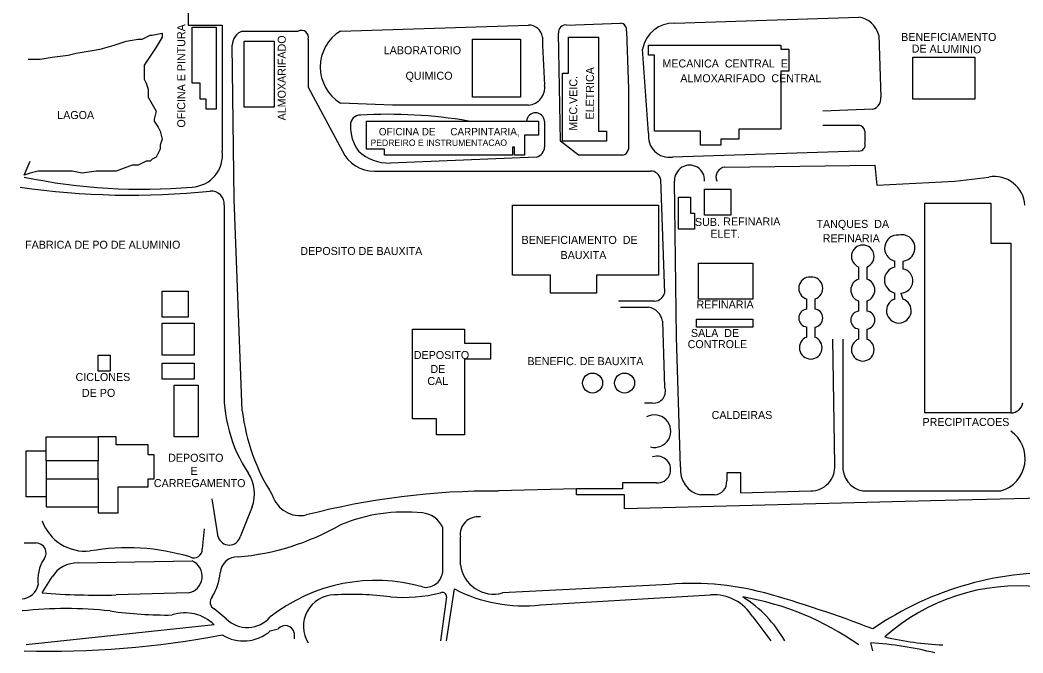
# Model space of a CAD drawing. Extents: x 325899 to 363134, y 7578590 to 7592502.
# Drawn here: x 335293 to 335794, y 7583508 to 7583824 of the extents above; entities that cross this region are included whole.
import ezdxf

# ---------------------------------------------------------------- set-up
doc = ezdxf.new("R2010")
doc.units = 0
for name, color, linetype in [('EDIFEXISTENT', 7, 'Continuous'), ('EDIFIDENTIF', 7, 'Continuous'), ('EDIFOBRAEXIS', 7, 'Continuous')]:
    doc.layers.add(name, color=color, linetype=linetype)

msp = doc.modelspace()

# ---------------------------------------------------------------- linework, layer by layer
at = {"layer": 'EDIFEXISTENT'}
for p, q in [((335379.39, 7583820.91), (335391.39, 7583820.91)), ((335379.39, 7583792.91), (335379.39, 7583820.91)), ((335391.39, 7583820.91), (335391.39, 7583779.91)), ((335405.39, 7583813.91), (335420.39, 7583813.91)), ((335405.39, 7583780.91), (335405.39, 7583813.91)), ((335420.39, 7583813.91), (335420.39, 7583780.91)), ((335519.39, 7583814.91), (335543.39, 7583814.91)), ((335519.39, 7583785.91), (335519.39, 7583814.91)), ((335543.39, 7583814.91), (335543.39, 7583785.91)), ((335567.39, 7583815.91), (335582.39, 7583815.91)), ((335567.39, 7583797.91), (335567.39, 7583815.91)), ((335582.39, 7583815.91), (335582.39, 7583768.91)), ((335607.39, 7583811.91), (335673.39, 7583811.91)), ((335607.39, 7583806.91), (335607.39, 7583811.91)), ((335673.39, 7583811.91), (335673.39, 7583809.91)), ((335673.39, 7583809.91), (335677.39, 7583809.91)), ((335677.39, 7583809.91), (335677.39, 7583798.91)), ((335610.39, 7583806.91), (335607.39, 7583806.91)), ((335610.39, 7583768.91), (335610.39, 7583806.91)), ((335739.39, 7583805.91), (335770.39, 7583805.91)), ((335739.39, 7583784.91), (335739.39, 7583805.91)), ((335770.39, 7583805.91), (335770.39, 7583784.91)), ((335564.39, 7583763.91), (335564.39, 7583797.91)), ((335564.39, 7583797.91), (335567.39, 7583797.91)), ((335677.39, 7583798.91), (335673.39, 7583798.91)), ((335673.39, 7583798.91), (335673.39, 7583769.91)), ((335383.39, 7583792.91), (335379.39, 7583792.91)), ((335383.39, 7583784.91), (335383.39, 7583792.91)), ((335386.39, 7583784.91), (335383.39, 7583784.91)), ((335386.39, 7583779.91), (335386.39, 7583784.91)), ((335543.39, 7583785.91), (335519.39, 7583785.91)), ((335770.39, 7583784.91), (335739.39, 7583784.91)), ((335391.39, 7583779.91), (335386.39, 7583779.91)), ((335420.39, 7583780.91), (335405.39, 7583780.91)), ((335466.39, 7583759.91), (335466.39, 7583773.91)), ((335466.39, 7583773.91), (335550.39, 7583773.91)), ((335550.39, 7583773.91), (335552.39, 7583773.91)), ((335552.39, 7583773.91), (335552.39, 7583766.91)), ((335582.39, 7583768.91), (335586.39, 7583768.91)), ((335586.39, 7583768.91), (335586.39, 7583763.91)), ((335633.39, 7583768.91), (335610.39, 7583768.91)), ((335633.39, 7583761.91), (335633.39, 7583768.91)), ((335673.39, 7583769.91), (335652.39, 7583769.91)), ((335652.39, 7583769.91), (335652.39, 7583764.91)), ((335552.39, 7583766.91), (335545.39, 7583766.91)), ((335545.39, 7583766.91), (335545.39, 7583756.91)), ((335586.39, 7583763.91), (335564.39, 7583763.91)), ((335652.39, 7583764.91), (335643.39, 7583764.91)), ((335643.39, 7583764.91), (335643.39, 7583761.91)), ((335475.39, 7583759.91), (335466.39, 7583759.91)), ((335475.39, 7583756.91), (335475.39, 7583759.91)), ((335540.39, 7583760.91), (335539.39, 7583760.91)), ((335539.39, 7583760.91), (335539.39, 7583756.91)), ((335540.39, 7583756.91), (335540.39, 7583760.91)), ((335643.39, 7583761.91), (335633.39, 7583761.91)), ((335539.39, 7583756.91), (335475.39, 7583756.91)), ((335545.39, 7583756.91), (335540.39, 7583756.91)), ((335635.39, 7583726.91), (335635.39, 7583739.91)), ((335635.39, 7583739.91), (335648.39, 7583739.91)), ((335648.39, 7583739.91), (335648.39, 7583726.91)), ((335622.39, 7583735.91), (335628.39, 7583735.91)), ((335622.39, 7583719.91), (335622.39, 7583735.91)), ((335628.39, 7583735.91), (335628.39, 7583727.91)), ((335745.39, 7583732.91), (335778.39, 7583732.91)), ((335745.39, 7583627.91), (335745.39, 7583732.91)), ((335778.39, 7583732.91), (335778.39, 7583712.91)), ((335539.39, 7583731.91), (335612.39, 7583731.91)), ((335539.39, 7583696.91), (335539.39, 7583731.91)), ((335612.39, 7583731.91), (335612.39, 7583696.91)), ((335628.39, 7583727.91), (335630.39, 7583727.91)), ((335630.39, 7583727.91), (335630.39, 7583719.91)), ((335648.39, 7583726.91), (335635.39, 7583726.91)), ((335630.39, 7583719.91), (335622.39, 7583719.91)), ((335778.39, 7583712.91), (335788.39, 7583712.91)), ((335788.39, 7583712.91), (335788.39, 7583627.91)), ((335632.39, 7583702.91), (335659.39, 7583702.91)), ((335632.39, 7583684.91), (335632.39, 7583702.91)), ((335659.39, 7583702.91), (335659.39, 7583684.91)), ((335730.39, 7583700.91), (335730.39, 7583703.91)), ((335734.39, 7583703.91), (335734.39, 7583699.91)), ((335712.39, 7583694.91), (335712.39, 7583700.91)), ((335716.39, 7583700.91), (335716.39, 7583694.91)), ((335558.39, 7583696.91), (335539.39, 7583696.91)), ((335558.39, 7583687.91), (335558.39, 7583696.91)), ((335612.39, 7583696.91), (335581.39, 7583696.91)), ((335581.39, 7583696.91), (335581.39, 7583687.91)), ((335364.39, 7583688.91), (335377.39, 7583688.91)), ((335364.39, 7583675.91), (335364.39, 7583688.91)), ((335377.39, 7583688.91), (335377.39, 7583675.91)), ((335581.39, 7583687.91), (335558.39, 7583687.91)), ((335730.39, 7583684.91), (335730.39, 7583687.91)), ((335733.39, 7583687.91), (335734.39, 7583684.91)), ((335659.39, 7583684.91), (335632.39, 7583684.91)), ((335686.39, 7583679.91), (335686.39, 7583684.91)), ((335690.39, 7583684.91), (335690.39, 7583679.91)), ((335712.39, 7583678.91), (335712.39, 7583683.91)), ((335716.39, 7583683.91), (335716.39, 7583678.91)), ((335377.39, 7583675.91), (335364.39, 7583675.91)), ((335364.39, 7583672.91), (335380.39, 7583672.91)), ((335364.39, 7583656.91), (335364.39, 7583672.91)), ((335380.39, 7583672.91), (335380.39, 7583656.91)), ((335631.39, 7583674.91), (335659.39, 7583674.91)), ((335631.39, 7583670.91), (335631.39, 7583674.91)), ((335659.39, 7583674.91), (335659.39, 7583670.91)), ((335489.39, 7583669.91), (335515.39, 7583669.91)), ((335489.39, 7583624.91), (335489.39, 7583669.91)), ((335515.39, 7583669.91), (335515.39, 7583662.91)), ((335659.39, 7583670.91), (335631.39, 7583670.91)), ((335686.39, 7583665.91), (335686.39, 7583670.91)), ((335690.39, 7583670.91), (335690.39, 7583665.91)), ((335712.39, 7583664.91), (335712.39, 7583669.91)), ((335716.39, 7583669.91), (335716.39, 7583664.91)), ((335515.39, 7583662.91), (335528.39, 7583662.91)), ((335528.39, 7583662.91), (335528.39, 7583654.91)), ((335332.39, 7583656.91), (335338.39, 7583656.91)), ((335332.39, 7583648.91), (335332.39, 7583656.91)), ((335338.39, 7583656.91), (335338.39, 7583648.91)), ((335380.39, 7583656.91), (335364.39, 7583656.91)), ((335364.39, 7583656.91), (335364.39, 7583656.91)), ((335364.39, 7583652.91), (335380.39, 7583652.91)), ((335364.39, 7583644.91), (335364.39, 7583652.91)), ((335380.39, 7583652.91), (335380.39, 7583644.91)), ((335528.39, 7583654.91), (335515.39, 7583654.91)), ((335515.39, 7583654.91), (335515.39, 7583623.91)), ((335338.39, 7583648.91), (335332.39, 7583648.91)), ((335380.39, 7583644.91), (335364.39, 7583644.91)), ((335370.39, 7583641.91), (335382.39, 7583641.91)), ((335370.39, 7583615.91), (335370.39, 7583641.91)), ((335382.39, 7583641.91), (335382.39, 7583615.91)), ((335788.39, 7583627.91), (335745.39, 7583627.91)), ((335501.39, 7583624.91), (335489.39, 7583624.91)), ((335501.39, 7583616.91), (335501.39, 7583624.91)), ((335515.39, 7583623.91), (335515.39, 7583622.91)), ((335515.39, 7583622.91), (335515.39, 7583616.91)), ((335306.39, 7583608.91), (335306.39, 7583615.91)), ((335306.39, 7583615.91), (335332.39, 7583615.91)), ((335332.39, 7583615.91), (335332.39, 7583603.91)), ((335341.39, 7583615.91), (335332.39, 7583615.91)), ((335341.39, 7583611.91), (335341.39, 7583615.91)), ((335382.39, 7583615.91), (335370.39, 7583615.91)), ((335515.39, 7583616.91), (335501.39, 7583616.91)), ((335296.39, 7583585.91), (335296.39, 7583608.91)), ((335296.39, 7583608.91), (335306.39, 7583608.91)), ((335306.39, 7583603.91), (335306.39, 7583608.91)), ((335357.39, 7583611.91), (335341.39, 7583611.91)), ((335357.39, 7583606.91), (335357.39, 7583611.91)), ((335332.39, 7583603.91), (335306.39, 7583603.91)), ((335306.39, 7583603.91), (335306.39, 7583594.91)), ((335332.39, 7583594.91), (335332.39, 7583603.91)), ((335360.39, 7583606.91), (335357.39, 7583606.91)), ((335360.39, 7583594.91), (335360.39, 7583606.91)), ((335306.39, 7583594.91), (335332.39, 7583594.91)), ((335306.39, 7583594.91), (335306.39, 7583585.91)), ((335332.39, 7583594.91), (335332.39, 7583580.91)), ((335357.39, 7583590.91), (335357.39, 7583594.91)), ((335357.39, 7583594.91), (335360.39, 7583594.91)), ((335342.39, 7583577.91), (335342.39, 7583590.91)), ((335342.39, 7583590.91), (335357.39, 7583590.91)), ((335306.39, 7583585.91), (335296.39, 7583585.91)), ((335306.39, 7583585.91), (335306.39, 7583580.91)), ((335306.39, 7583580.91), (335332.39, 7583580.91)), ((335332.39, 7583580.91), (335332.39, 7583577.91)), ((335332.39, 7583577.91), (335342.39, 7583577.91))]:
    msp.add_line(p, q, dxfattribs=at)
for centre in [(335579.39, 7583642.91), (335595.39, 7583642.91)]:
    msp.add_circle(centre, 5, dxfattribs=at)
for centre, radius, start, end in [((335731.9, 7583710.33), 6.6, 85.7202, 256.7875), ((335733.85, 7583710.48), 6.59, 274.7414, 102.7509), ((335714.39, 7583706.23), 5.68, 290.6097, 249.3903), ((335731.86, 7583694.41), 6.66, 102.7386, 257.2614), ((335733.35, 7583693.96), 6.05, 270.4308, 80.0419), ((335688.02, 7583690.3), 5.63, 86.1782, 253.2121), ((335688.79, 7583690.3), 5.62, 286.5373, 94.0723), ((335714.17, 7583689.41), 5.78, 107.9453, 252.0547), ((335714.64, 7583689.41), 5.77, 287.6501, 72.3499), ((335732.39, 7583679.08), 6.17, 108.9246, 71.0754), ((335686.92, 7583675.41), 4.53, 96.7329, 263.2671), ((335689.89, 7583675.41), 4.53, 276.3402, 83.6598), ((335712.92, 7583674.41), 4.53, 96.7329, 263.2671), ((335715.89, 7583674.41), 4.53, 276.3402, 83.6598), ((335688.39, 7583660.59), 5.68, 110.6097, 69.3903), ((335714.39, 7583659.59), 5.68, 110.6097, 69.3903)]:
    msp.add_arc(centre, radius, start, end, dxfattribs=at)
at = {"layer": 'EDIFOBRAEXIS'}
for points in [[(335400.39, 7584001.91), (335410.39, 7583884.91), (335420.39, 7583864.91), (335395.39, 7583838.91), (335395.39, 7583828.91), (335377.39, 7583828.91), (335377.39, 7583821.91), (335394.39, 7583821.91), (335394.39, 7583758.91)], [(335566.39, 7583821.91), (335593.39, 7583822.91)], [(335620.39, 7583822.91), (335712.39, 7583825.91)], [(335297.39, 7583804.91), (335303.39, 7583804.91), (335309.39, 7583805.91), (335317.39, 7583806.91), (335321.39, 7583807.91), (335327.39, 7583808.91), (335333.39, 7583809.91), (335340.39, 7583811.91), (335346.39, 7583813.91), (335352.39, 7583814.91), (335354.39, 7583814.91), (335358.39, 7583816.91), (335359.39, 7583816.91), (335364.39, 7583817.91), (335364.39, 7583815.91), (335361.39, 7583810.91), (335359.39, 7583807.91), (335357.39, 7583804.91), (335355.39, 7583801.91), (335355.39, 7583799.91), (335355.39, 7583796.91), (335355.39, 7583794.91), (335356.39, 7583792.91), (335357.39, 7583789.91), (335357.39, 7583785.91), (335361.39, 7583778.91), (335360.39, 7583774.91), (335360.39, 7583773.91), (335362.39, 7583770.91), (335363.39, 7583768.91), (335364.39, 7583764.91), (335363.39, 7583761.91), (335363.39, 7583759.91), (335362.39, 7583757.91), (335361.39, 7583755.91), (335359.39, 7583754.91), (335358.39, 7583753.91), (335356.39, 7583753.91), (335352.39, 7583751.91), (335349.39, 7583751.91), (335341.39, 7583748.91), (335331.39, 7583748.91), (335324.39, 7583747.91), (335319.39, 7583748.91), (335312.39, 7583748.91), (335305.39, 7583748.91), (335302.39, 7583748.91), (335298.39, 7583747.91), (335295.39, 7583746.91), (335298.39, 7583753.91)], [(335404.39, 7583818.91), (335432.39, 7583818.91)], [(335453.39, 7583818.91), (335547.39, 7583821.91)], [(335572.39, 7583756.91), (335563.39, 7583763.91), (335562.39, 7583817.91)], [(335596.39, 7583818.91), (335597.39, 7583789.91), (335597.39, 7583759.91)], [(335437.39, 7583814.91), (335437.39, 7583790.91), (335454.39, 7583758.91)], [(335554.39, 7583815.91), (335554.39, 7583811.91), (335555.39, 7583791.91)], [(335722.39, 7583816.91), (335723.39, 7583785.91)], [(335404.39, 7583628.91), (335400.39, 7583734.91), (335399.39, 7583811.91)], [(335607.39, 7583767.91), (335604.39, 7583809.91)], [(335479.39, 7583781.91), (335453.39, 7583782.91)], [(335547.39, 7583781.91), (335479.39, 7583781.91)], [(335719.39, 7583779.91), (335694.39, 7583778.91)], [(335555.39, 7583773.91), (335555.39, 7583760.91)], [(335694.39, 7583771.91), (335712.39, 7583771.91)], [(335715.39, 7583768.91), (335715.39, 7583762.91)], [(335712.39, 7583758.91), (335619.39, 7583755.91)], [(335551.39, 7583755.91), (335478.39, 7583752.91)], [(335594.39, 7583756.91), (335572.39, 7583756.91)], [(335470.39, 7583748.91), (335608.39, 7583748.91)], [(335645.39, 7583750.91), (335720.39, 7583751.91), (335721.39, 7583741.91), (335760.39, 7583743.91), (335777.39, 7583745.91)], [(335613.39, 7583744.91), (335615.39, 7583687.91)], [(335623.39, 7583600.91), (335621.39, 7583665.91), (335620.39, 7583743.91)], [(335635.39, 7583743.91), (335635.39, 7583743.91)], [(335641.39, 7583743.91), (335641.39, 7583743.91)], [(335395.39, 7583731.91), (335395.39, 7583641.91)], [(335610.39, 7583683.91), (335592.39, 7583683.91)], [(335593.39, 7583680.91), (335607.39, 7583680.91)], [(335614.39, 7583673.91), (335615.39, 7583640.91)], [(335700.39, 7583601.91), (335699.39, 7583664.91)], [(335704.39, 7583664.91), (335704.39, 7583601.91)], [(335609.39, 7583632.91), (335605.39, 7583632.91)], [(335653.39, 7583587.91), (335653.39, 7583597.91), (335646.39, 7583597.91), (335646.39, 7583593.91)], [(336081.39, 7583591.91), (335748.39, 7583583.91), (335595.39, 7583579.91), (335595.39, 7583586.91), (335571.39, 7583586.91), (335571.39, 7583589.91), (335532.39, 7583588.91)], [(335611.39, 7583592.91), (335594.39, 7583592.91), (335594.39, 7583589.91), (335571.39, 7583589.91)], [(335640.39, 7583586.91), (335633.39, 7583586.91)], [(335653.39, 7583587.91), (335688.39, 7583588.91)], [(335714.39, 7583588.91), (335783.39, 7583588.91)], [(335392.39, 7583565.91), (335389.39, 7583584.91)], [(335409.39, 7583580.91), (335403.39, 7583565.91)], [(335385.39, 7583569.91), (335384.39, 7583559.91)], [(335504.39, 7583570.91), (335504.39, 7583547.91)], [(335295.39, 7583562.91), (335301.39, 7583562.91)], [(335513.39, 7583551.91), (335513.39, 7583565.91)], [(335322.39, 7583552.91), (335379.39, 7583553.91)], [(335304.39, 7583537.91), (335309.39, 7583545.91)], [(335614.39, 7583541.91), (335534.39, 7583537.91)], [(335377.39, 7583537.91), (335341.39, 7583536.91)], [(335506.39, 7583513.91), (335510.39, 7583539.91)], [(335553.39, 7583531.91), (335638.39, 7583536.91)], [(335506.39, 7583535.91), (335503.39, 7583513.91)], [(335396.39, 7583524.91), (335390.39, 7583529.91)], [(335390.39, 7583521.91), (335296.39, 7583511.91)], [(335659.39, 7583525.91), (335668.39, 7583513.91)], [(335418.39, 7583518.91), (335418.39, 7583518.91), (335422.39, 7583519.91)], [(335430.39, 7583517.91), (335430.39, 7583514.91)], [(335719.39, 7583508.91), (335718.39, 7583512.91)]]:
    msp.add_lwpolyline(points, dxfattribs=at)
for centre, radius, start, end in [((335592.89, 7583819.41), 3.54, 351.8881, 81.8517), ((335619.88, 7583807.2), 15.72, 88.1316, 170.0561), ((335710.48, 7583813.73), 12.33, 14.9562, 81.0694), ((335406.98, 7583811.78), 7.59, 109.9538, 178.9708), ((335433.89, 7583815.66), 3.58, 347.9052, 114.7751), ((335464.54, 7583800.91), 21.17, 121.7759, 238.2241), ((335547.33, 7583814.75), 7.16, 9.3083, 89.4891), ((335565.89, 7583818.41), 3.54, 81.8699, 188.1301), ((335546.81, 7583790.58), 8.69, 273.8506, 8.8297), ((335718.06, 7583785.13), 5.39, 284.2813, 8.3386), ((335476.89, 7583532.41), 244.87, 80.48, 93.1604), ((335550.89, 7583773.52), 4.52, 4.9545, 175.0455), ((335463.39, 7583771.91), 5, 90, 180), ((335479.89, 7583771.41), 21.51, 178.6678, 215.5377), ((335617.73, 7583766.25), 10.47, 170.8377, 279.1623), ((335711.89, 7583768.41), 3.54, 8.1301, 81.8699), ((335712.56, 7583761.91), 3, 266.8202, 19.44), ((335378.52, 7583756.89), 16, 273.1119, 7.277), ((335470.18, 7583766.37), 17.46, 205.2952, 270.6941), ((335477.68, 7583775.34), 22.44, 227.0604, 271.8275), ((335550.14, 7583761.02), 5.25, 283.7986, 358.8818), ((335593.97, 7583760.33), 3.44, 276.9656, 353.0344), ((335608.32, 7583743.7), 5.21, 13.4652, 89.2152), ((335627.89, 7583744.35), 7.51, 356.6707, 183.3293), ((335646.19, 7583745.81), 5.16, 98.885, 201.6253), ((335354.15, 7584024.99), 285.19, 258.1098, 275.0773), ((335780.09, 7583730.81), 15.34, 4.1317, 100.1183), ((335348.81, 7584115.9), 379.06, 261.5937, 275.9942), ((335388.89, 7583732.41), 6.52, 355.6013, 94.3987), ((335610.23, 7583689.25), 5.34, 271.7899, 345.5297), ((335605.39, 7583671.91), 9.22, 12.5288, 77.4712), ((335467.39, 7583637.91), 72.11, 176.8202, 213.6901), ((335609.91, 7583638.77), 5.88, 264.9317, 21.3285), ((335788.22, 7583634.22), 6.31, 271.5557, 348.0555), ((335505.13, 7583641.21), 101.48, 186.9607, 212.3469), ((335610.34, 7583618.81), 8.13, 256.1469, 119.0424), ((335778.62, 7583605.12), 16.9, 286.4026, 54.6728), ((335611.69, 7583599.61), 6.71, 267.4362, 110.0561), ((335391.63, 7583587.44), 18.92, 339.8136, 33.6061), ((335635.78, 7583599.19), 12.51, 172.0858, 258.9895), ((335688.38, 7583600.96), 12.05, 270.04, 4.5412), ((335716.67, 7583601.01), 12.31, 175.8131, 259.3241), ((335639.89, 7583593.41), 6.52, 274.3987, 4.3987), ((335433.32, 7583591.15), 14.56, 196.9027, 282.1662), ((335530.32, 7583215.46), 373.45, 89.6826, 104.5675), ((335485.5, 7583495.59), 82.8, 83.8359, 112.8154), ((335493.31, 7583565.73), 12.23, 25.0765, 84.9395), ((335326.05, 7583581.87), 23.07, 200.1663, 275.8229), ((335390.81, 7583682.11), 126.73, 275.2434, 299.5926), ((335522.09, 7583567.21), 8.8, 81.5014, 188.4986), ((335301.39, 7583557.91), 5, 323.1301, 90), ((335397.89, 7583567.66), 5.77, 197.6501, 342.3499), ((335347.01, 7583450.98), 109.52, 73.3473, 99.7855), ((335380.25, 7583559.63), 4.15, 243.4349, 3.9452), ((335321.53, 7583544.34), 19.3, 146.7805, 187.2302), ((335321.73, 7583538.58), 14.35, 87.337, 149.2645), ((335375.98, 7583546.21), 8.42, 279.6837, 66.0663), ((335401.89, 7583547.41), 8.51, 86.6335, 176.6335), ((335530.01, 7583554.1), 16.76, 187.4813, 285.1385), ((335364.39, 7583550.91), 29.15, 329.0362, 354.0939), ((335496.11, 7583549.1), 8.37, 258.1444, 351.8396), ((335810.31, 7583387.78), 160.39, 86.7534, 124.5311), ((335293.79, 7583543.68), 8.78, 273.9511, 348.4208), ((335471.04, 7583459.2), 84.98, 74.0499, 128.2799), ((335628.97, 7583400.71), 141.96, 75.1348, 95.8959), ((335333.39, 7583925.91), 389.08, 265.7255, 271.1782), ((335450.6, 7583521.28), 15.63, 90.7546, 212.3596), ((335459.39, 7583396.41), 140.79, 82.244, 93.6652), ((335484.39, 7583618.16), 82.47, 265.8278, 283.3201), ((335504.39, 7583536.16), 2.02, 352.875, 119.7449), ((335545.14, 7583607.12), 75.66, 242.6603, 276.2613), ((335639.98, 7583514.4), 22.57, 30.6717, 94.0364), ((335506.89, 7582972.41), 587.29, 68.78738, 74.34272), ((335792.14, 7583441.4), 100.04, 84.1201, 131.8546), ((335392.23, 7583533.3), 3.85, 137.3373, 241.5873), ((335622.07, 7583484.04), 61.12, 29.2611, 58.0745), ((335631.04, 7583397.4), 140.46, 54.6096, 80.4316), ((335316.39, 7583327.91), 202.2, 83.7537, 96.2463), ((335366.23, 7583719.08), 192.19, 261.6732, 270.9441), ((335375.89, 7583507.61), 20.37, 44.6021, 108.6129), ((335406.91, 7583535.95), 15.25, 226.3837, 318.8214), ((335306.92, 7583982.84), 474.07, 268.6068, 280.633), ((335405.03, 7583534.25), 20.34, 238.471, 311.0563), ((335425.94, 7583517.11), 4.52, 10.1915, 141.736), ((335709.58, 7583351.64), 161.51, 75.3648, 86.8739), ((335761.68, 7583671.89), 160.14, 256.9023, 267.391)]:
    msp.add_arc(centre, radius, start, end, dxfattribs=at)

# ---------------------------------------------------------------- texts
at = {"layer": 'EDIFIDENTIF'}
for s, rotation, p in [('OFICINA E PINTURA', 90, (335375.91, 7583770.63)), ('ALMOXARIFADO', 90, (335426.12, 7583774.23)), ('DE ALUMINIO', 359.3338, (335738.79, 7583808.16)), ('ELETRICA', 89.7736, (335579.99, 7583774.67)), ('MEC.VEIC.', 89.7736, (335571.7, 7583769.1)), ('BENEFICIAMENTO  DE', 359.9692, (335543.94, 7583712.48))]:
    msp.add_text(s, height=4, rotation=rotation, dxfattribs=at).set_placement(p)
for s, height, p in [('BENEFICIAMENTO', 4, (335733.57, 7583813.94)), ('LABORATORIO', 4, (335475.07, 7583807.31)), ('MECANICA  CENTRAL  E', 4, (335614.28, 7583800.69)), ('QUIMICO', 4, (335485.97, 7583794.56)), ('ALMOXARIFADO  CENTRAL', 4, (335623.23, 7583793.3)), ('LAGOA', 4, (335311.96, 7583774.91)), ('OFICINA DE', 3.7, (335472.63, 7583766.73)), ('CARPINTARIA,', 3.7, (335508.33, 7583766.74)), ('PEDREIRO E INSTRUMENTACAO', 3.2221, (335468.44, 7583761.45)), ('SUB.', 4, (335630.53, 7583721.45)), ('REFINARIA', 4, (335644.68, 7583721.68)), ('TANQUES  DA', 4, (335691.25, 7583720.47)), ('ELET.', 4, (335638.24, 7583715.52)), ('REFINARIA', 4, (335694.35, 7583713.28)), ('FABRICA DE PO DE ALUMINIO', 4, (335295.91, 7583710.06)), ('DEPOSITO DE BAUXITA', 4, (335433.39, 7583706.91)), ('BAUXITA', 4, (335563.39, 7583704.91)), ('REFINARIA', 4, (335631.34, 7583680.17)), ('SALA  DE', 4, (335628.53, 7583665.91)), ('CONTROLE', 4, (335626.89, 7583660.35)), ('DEPOSITO', 4, (335490.11, 7583654.91)), ('BENEFIC. DE BAUXITA', 4, (335546.84, 7583651.84)), ('CICLONES', 4, (335321.11, 7583643.91)), ('DE', 4, (335498.39, 7583647.91)), ('CAL', 4, (335496.87, 7583641.91)), ('DE PO', 4, (335324.31, 7583635.96)), ('CALDEIRAS', 4, (335638.87, 7583624.91)), ('PRECIPITACOES', 4, (335744.21, 7583621.42)), ('DEPOSITO', 4, (335367.36, 7583603.51)), ('E', 4, (335378.56, 7583596.98)), ('CARREGAMENTO', 4, (335360.23, 7583590.85))]:
    msp.add_text(s, height=height, dxfattribs=at).set_placement(p)

doc.saveas('drawing.dxf')
